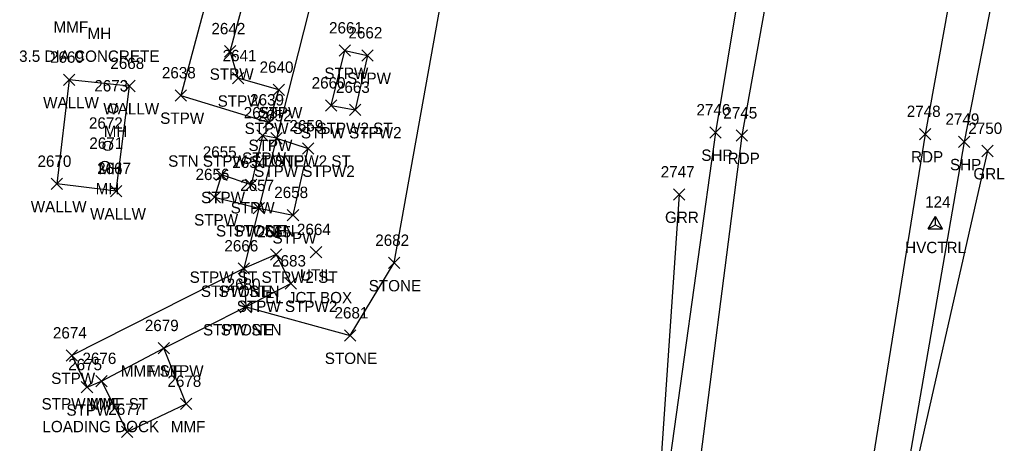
# Model space of a CAD drawing. Extents: x 1443071 to 1445292, y 614024 to 622563.
# Drawn here: x 1443946.8 to 1444119.8, y 620105.8 to 620180.3 of the extents above; entities that cross this region are included whole.
import ezdxf

# ---------------------------------------------------------------- set-up
doc = ezdxf.new("R2010")
doc.units = 0
for name, color, linetype in [('C_A', 7, 'Continuous'), ('C_I', 7, 'Continuous'), ('CPSM', 7, 'Continuous'), ('L_A', 7, 'Continuous'), ('L_C', 7, 'Continuous'), ('L_I', 7, 'Continuous'), ('L_TIC', 7, 'Continuous'), ('LASF', 7, 'Continuous'), ('LBF', 7, 'Continuous'), ('LDEFAULT', 7, 'Continuous'), ('LW', 7, 'Continuous'), ('P_A', 7, 'Continuous'), ('P_I', 7, 'Continuous'), ('P_TIC', 7, 'Continuous'), ('PET', 7, 'Continuous'), ('PSP', 7, 'Continuous'), ('R_A', 7, 'Continuous'), ('R_I', 7, 'Continuous'), ('R_TIC', 7, 'Continuous'), ('RGR', 7, 'Continuous'), ('U_A', 7, 'Continuous'), ('U_C', 7, 'Continuous'), ('U_I', 7, 'Continuous'), ('UDEFAULT', 7, 'Continuous'), ('UUMH', 7, 'Continuous')]:
    doc.layers.add(name, color=color, linetype=linetype)

msp = doc.modelspace()

# ---------------------------------------------------------------- linework, layer by layer
at = {"layer": 'CPSM'}
for p, q in [((1444106.46, 620143.5), (1444107.71, 620145.66)), ((1444106.46, 620143.5), (1444107.71, 620144.22)), ((1444108.96, 620143.5), (1444107.71, 620145.66)), ((1444107.71, 620144.22), (1444107.71, 620145.66)), ((1444107.71, 620144.22), (1444107.71, 620144.22)), ((1444107.71, 620144.22), (1444108.96, 620143.5)), ((1444106.46, 620143.5), (1444108.96, 620143.5))]:
    msp.add_line(p, q, dxfattribs=at)
at = {"layer": 'L_TIC'}
for points in [[(1443982.8, 620173.72), (1443984.8, 620175.72)], [(1443984.8, 620173.72), (1443982.8, 620175.72)], [(1444002.96, 620173.86), (1444004.96, 620175.86)], [(1444004.96, 620173.86), (1444002.96, 620175.86)], [(1444006.94, 620172.99), (1444008.94, 620174.99)], [(1444008.94, 620172.99), (1444006.94, 620174.99)], [(1443954.51, 620168.71), (1443956.51, 620170.71)], [(1443956.51, 620168.71), (1443954.51, 620170.71)], [(1443984.21, 620168.98), (1443986.21, 620170.98)], [(1443986.21, 620168.98), (1443984.21, 620170.98)], [(1443965.09, 620167.62), (1443967.09, 620169.62)], [(1443967.09, 620167.62), (1443965.09, 620169.62)], [(1443991.36, 620166.94), (1443993.36, 620168.94)], [(1443993.36, 620166.94), (1443991.36, 620168.94)], [(1443974.11, 620165.96), (1443976.11, 620167.96)], [(1443976.11, 620165.96), (1443974.11, 620167.96)], [(1444000.56, 620164.18), (1444002.56, 620166.18)], [(1444002.56, 620164.18), (1444000.56, 620166.18)], [(1444000.56, 620164.18), (1444002.56, 620166.18)], [(1444002.56, 620164.18), (1444000.56, 620166.18)], [(1444004.74, 620163.41), (1444006.74, 620165.41)], [(1444006.74, 620163.41), (1444004.74, 620165.41)], [(1444004.74, 620163.41), (1444006.74, 620165.41)], [(1444006.74, 620163.41), (1444004.74, 620165.41)], [(1443989.62, 620161.19), (1443991.62, 620163.19)], [(1443991.62, 620161.19), (1443989.62, 620163.19)], [(1443988.49, 620158.93), (1443990.49, 620160.93)], [(1443990.49, 620158.93), (1443988.49, 620160.93)], [(1443990.95, 620158.42), (1443992.95, 620160.42)], [(1443992.95, 620158.42), (1443990.95, 620160.42)], [(1443990.95, 620158.42), (1443992.95, 620160.42)], [(1443992.95, 620158.42), (1443990.95, 620160.42)], [(1443990.95, 620158.42), (1443992.95, 620160.42)], [(1443992.95, 620158.42), (1443990.95, 620160.42)], [(1443996.52, 620156.64), (1443998.52, 620158.64)], [(1443998.52, 620156.64), (1443996.52, 620158.64)], [(1443996.52, 620156.64), (1443998.52, 620158.64)], [(1443998.52, 620156.64), (1443996.52, 620158.64)], [(1443981.29, 620152.01), (1443983.29, 620154.01)], [(1443983.29, 620152.01), (1443981.29, 620154.01)], [(1443952.34, 620150.4), (1443954.34, 620152.4)], [(1443954.34, 620150.4), (1443952.34, 620152.4)], [(1443952.34, 620150.4), (1443954.34, 620152.4)], [(1443954.34, 620150.4), (1443952.34, 620152.4)], [(1443962.77, 620149.14), (1443964.77, 620151.14)], [(1443964.77, 620149.14), (1443962.77, 620151.14)], [(1443962.77, 620149.14), (1443964.77, 620151.14)], [(1443964.77, 620149.14), (1443962.77, 620151.14)], [(1443986.49, 620150.21), (1443988.49, 620152.21)], [(1443988.49, 620150.21), (1443986.49, 620152.21)], [(1443980.07, 620148.08), (1443982.07, 620150.08)], [(1443982.07, 620148.08), (1443980.07, 620150.08)], [(1443987.85, 620146.15), (1443989.85, 620148.15)], [(1443989.85, 620146.15), (1443987.85, 620148.15)], [(1443987.85, 620146.15), (1443989.85, 620148.15)], [(1443989.85, 620146.15), (1443987.85, 620148.15)], [(1443993.84, 620144.91), (1443995.84, 620146.91)], [(1443995.84, 620144.91), (1443993.84, 620146.91)], [(1443990.9, 620138), (1443992.9, 620140)], [(1443992.9, 620138), (1443990.9, 620140)], [(1443990.9, 620138), (1443992.9, 620140)], [(1443992.9, 620138), (1443990.9, 620140)], [(1443985.19, 620135.52), (1443987.19, 620137.52)], [(1443987.19, 620135.52), (1443985.19, 620137.52)], [(1443985.19, 620135.52), (1443987.19, 620137.52)], [(1443987.19, 620135.52), (1443985.19, 620137.52)], [(1444011.6, 620136.5), (1444013.6, 620138.5)], [(1444013.6, 620136.5), (1444011.6, 620138.5)], [(1443993.47, 620132.87), (1443995.47, 620134.87)], [(1443995.47, 620132.87), (1443993.47, 620134.87)], [(1443993.47, 620132.87), (1443995.47, 620134.87)], [(1443995.47, 620132.87), (1443993.47, 620134.87)], [(1443985.57, 620128.75), (1443987.57, 620130.75)], [(1443987.57, 620128.75), (1443985.57, 620130.75)], [(1443985.57, 620128.75), (1443987.57, 620130.75)], [(1443987.57, 620128.75), (1443985.57, 620130.75)], [(1444003.87, 620123.73), (1444005.87, 620125.73)], [(1444005.87, 620123.73), (1444003.87, 620125.73)], [(1443971.12, 620121.51), (1443973.12, 620123.51)], [(1443973.12, 620121.51), (1443971.12, 620123.51)], [(1443971.12, 620121.51), (1443973.12, 620123.51)], [(1443973.12, 620121.51), (1443971.12, 620123.51)], [(1443954.95, 620120.21), (1443956.95, 620122.21)], [(1443956.95, 620120.21), (1443954.95, 620122.21)], [(1443957.64, 620114.63), (1443959.64, 620116.63)], [(1443959.64, 620114.63), (1443957.64, 620116.63)], [(1443960.2, 620115.72), (1443962.2, 620117.72)], [(1443962.2, 620115.72), (1443960.2, 620117.72)], [(1443960.2, 620115.72), (1443962.2, 620117.72)], [(1443962.2, 620115.72), (1443960.2, 620117.72)], [(1443975.08, 620111.7), (1443977.08, 620113.7)], [(1443977.08, 620111.7), (1443975.08, 620113.7)], [(1443964.69, 620106.77), (1443966.69, 620108.77)], [(1443966.69, 620106.77), (1443964.69, 620108.77)]]:
    msp.add_lwpolyline(points, dxfattribs=at)
at = {"layer": 'LASF'}
msp.add_lwpolyline([(1443976.5, 620204.31), (1443981.5, 620202.34), (1443985.13, 620204.36), (1443990.03, 620197.9), (1443997.43, 620196.31), (1443999.37, 620195.62), (1444001.92, 620195.04), (1443998.63, 620185.84), (1443991.95, 620159.42), (1443988.85, 620147.15), (1443986.19, 620136.52), (1443986.57, 620129.75), (1444004.87, 620124.73), (1444012.6, 620137.5), (1444022.51, 620192.75), (1444029.87, 620218.3), (1444026.72, 620219.74), (1444027.45, 620223.51), (1444031.72, 620223.15), (1444037.34, 620241.52)], dxfattribs=at)
at = {"layer": 'LBF'}
for points in [[(1443985.13, 620204.36), (1443975.11, 620166.96), (1443990.62, 620162.19), (1443992.36, 620167.94), (1443985.21, 620169.98), (1443983.8, 620174.72), (1443990.03, 620197.9)], [(1444001.56, 620165.18), (1444003.96, 620174.86), (1444007.94, 620173.99), (1444005.74, 620164.41)], [(1444001.56, 620165.18), (1444005.74, 620164.41)], [(1443991.95, 620159.42), (1443989.49, 620159.93), (1443987.49, 620151.21), (1443982.29, 620153.01), (1443981.07, 620149.08), (1443988.85, 620147.15), (1443994.84, 620145.91), (1443997.52, 620157.64)], [(1443991.95, 620159.42), (1443997.52, 620157.64)], [(1443991.9, 620139), (1443986.19, 620136.52), (1443955.95, 620121.21), (1443958.64, 620115.63), (1443961.2, 620116.72), (1443972.12, 620122.51), (1443986.57, 620129.75), (1443994.47, 620133.87)], [(1443991.9, 620139), (1443994.47, 620133.87)]]:
    msp.add_lwpolyline(points, dxfattribs=at)
at = {"layer": 'LDEFAULT'}
msp.add_lwpolyline([(1443961.2, 620116.72), (1443965.69, 620107.77), (1443976.08, 620112.7), (1443972.12, 620122.51)], dxfattribs=at)
at = {"layer": 'LW'}
for points in [[(1443963.77, 620150.14), (1443966.09, 620168.62), (1443955.51, 620169.71), (1443953.34, 620151.4)], [(1443963.77, 620150.14), (1443953.34, 620151.4)]]:
    msp.add_lwpolyline(points, dxfattribs=at)
at = {"layer": 'P_TIC'}
for points in [[(1444068.05, 620159.45), (1444070.05, 620161.45)], [(1444070.05, 620159.45), (1444068.05, 620161.45)], [(1444072.72, 620158.9), (1444074.72, 620160.9)], [(1444074.72, 620158.9), (1444072.72, 620160.9)], [(1444104.94, 620159.17), (1444106.94, 620161.17)], [(1444106.94, 620159.17), (1444104.94, 620161.17)], [(1444111.75, 620157.8), (1444113.75, 620159.8)], [(1444113.75, 620157.8), (1444111.75, 620159.8)]]:
    msp.add_lwpolyline(points, dxfattribs=at)
at = {"layer": 'PET'}
for points in [[(1444393.99, 621275.61), (1444360.23, 621155.32), (1444345.74, 621103.98), (1444299.41, 620941.8), (1444273.27, 620844.52), (1444244.09, 620730.97), (1444221.37, 620651.37), (1444196.75, 620548.06), (1444177.44, 620486.23), (1444161.6, 620423.84), (1444143.45, 620356.38), (1444122.97, 620254.68), (1444105.94, 620160.17), (1444094.56, 620089.52), (1444083.91, 620011.71), (1444077.6, 619958.52), (1444073.05, 619913.75)], [(1444350.41, 621238.76), (1444319.14, 621126.97), (1444291.55, 621028.33), (1444258.02, 620908.98), (1444225.45, 620794.19), (1444210.22, 620737.59), (1444176.75, 620619.09), (1444153.1, 620523.45), (1444139.28, 620467.17), (1444131.97, 620435.45), (1444113.12, 620363.38), (1444103.37, 620315.76), (1444093.47, 620268.1), (1444084.86, 620222.29), (1444073.72, 620159.9), (1444065.08, 620092.83), (1444054.27, 620016.44), (1444048.57, 619960.86), (1444043.42, 619916.17), (1444073.05, 619913.75)]]:
    msp.add_lwpolyline(points, dxfattribs=at)
at = {"layer": 'PSP'}
for points in [[(1444228.91, 620648.98), (1444202.76, 620547.52), (1444186.16, 620483.96), (1444170.45, 620422.38), (1444153.07, 620354.47), (1444132.16, 620257.26), (1444128.32, 620238.3), (1444112.75, 620158.8), (1444100.76, 620089.32), (1444087.94, 620010.71), (1444079.9, 619958.71), (1444074.06, 619920.41), (1444074.5, 619920), (1444074.51, 619919.99), (1444073.05, 619913.75)], [(1444173.15, 620620.17), (1444162.97, 620582.35), (1444145.76, 620516.18), (1444133.67, 620469.15), (1444125.56, 620436.17), (1444114.52, 620389.82), (1444108.73, 620364.47), (1444098.18, 620317.14), (1444089.01, 620271.12), (1444079.56, 620223.77), (1444069.05, 620160.45), (1444059.79, 620093.6), (1444051.39, 620014.62), (1444046.92, 619961.11), (1444044.18, 619924.22), (1444043.48, 619922.84), (1444043.42, 619916.17)]]:
    msp.add_lwpolyline(points, dxfattribs=at)
at = {"layer": 'R_TIC'}
for points in [[(1444115.85, 620156.19), (1444117.85, 620158.19)], [(1444117.85, 620156.19), (1444115.85, 620158.19)], [(1444061.71, 620148.53), (1444063.71, 620150.53)], [(1444063.71, 620148.53), (1444061.71, 620150.53)]]:
    msp.add_lwpolyline(points, dxfattribs=at)
at = {"layer": 'RGR'}
for points in [[(1444116.85, 620157.19), (1444101.49, 620089.2), (1444088.76, 620010.5), (1444080.64, 619958.46), (1444074.63, 619920.83)], [(1444062.71, 620149.53), (1444058.87, 620093.77), (1444050.68, 620014.64), (1444046.19, 619961.04), (1444043.36, 619924.56)]]:
    msp.add_lwpolyline(points, dxfattribs=at)
at = {"layer": 'UDEFAULT'}
for points in [[(1443997.88, 620138.4), (1443999.88, 620140.4)], [(1443999.88, 620138.4), (1443997.88, 620140.4)]]:
    msp.add_lwpolyline(points, dxfattribs=at)
at = {"layer": 'UUMH'}
for p, q in [((1443963.22, 620164.66), (1443963.22, 620164.66)), ((1443964.06, 620164.66), (1443964.06, 620164.66)), ((1443962.29, 620158.11), (1443962.29, 620158.11)), ((1443963.12, 620158.11), (1443963.12, 620158.11)), ((1443961.79, 620154.57), (1443961.79, 620154.57)), ((1443962.62, 620154.57), (1443962.62, 620154.57))]:
    msp.add_line(p, q, dxfattribs=at)
for centre in [(1443963.22, 620164.66), (1443962.29, 620158.11), (1443961.79, 620154.57)]:
    msp.add_circle(centre, 0.833, dxfattribs=at)

# ---------------------------------------------------------------- texts
at = {"layer": 'C_A'}
msp.add_text('HVCTRL', height=2, dxfattribs=at).set_placement((1444102.4, 620139.22))
at = {"layer": 'C_I'}
msp.add_text('124', height=2, dxfattribs=at).set_placement((1444105.91, 620147.22))
at = {"layer": 'L_A'}
for s, p in [('MMF', (1443952.76, 620177.99)), ('STPW', (1443980.2, 620169.72)), ('STPW', (1444000.35, 620169.86)), ('STPW', (1444004.33, 620168.99)), ('WALLW', (1443950.93, 620164.71)), ('STPW', (1443981.6, 620164.98)), ('WALLW', (1443961.51, 620163.62)), ('STPW', (1443988.76, 620162.94)), ('STPW', (1443971.5, 620161.96)), ('STPW ST STPW2 ST', (1443986.33, 620160.18)), ('STPW ST STPW2 ST', (1443986.33, 620160.18)), ('STPW STPW2', (1443996.23, 620159.41)), ('STPW STPW2', (1443996.23, 620159.41)), ('STPW', (1443987.01, 620157.19)), ('STN STPW ST STPW2 ST', (1443972.9, 620154.42)), ('STN STPW ST STPW2 ST', (1443972.9, 620154.42)), ('STPW', (1443985.88, 620154.93)), ('STONE', (1443987.49, 620154.42)), ('STPW STPW2', (1443988.01, 620152.64)), ('STPW STPW2', (1443988.01, 620152.64)), ('STPW', (1443978.68, 620148.01)), ('WALLW', (1443948.76, 620146.4)), ('WALLW', (1443948.76, 620146.4)), ('STPW', (1443983.88, 620146.21)), ('WALLW', (1443959.19, 620145.14)), ('WALLW', (1443959.19, 620145.14)), ('STPW', (1443977.46, 620144.08)), ('STPW STN', (1443981.3, 620142.15)), ('STONE', (1443984.4, 620142.15)), ('STPW', (1443991.24, 620140.91)), ('STPW ST STPW2 ST', (1443976.67, 620134)), ('STPW ST STPW2 ST', (1443976.67, 620134)), ('STONE', (1444008.14, 620132.5)), ('STPW STN', (1443978.64, 620131.52)), ('STONE', (1443981.74, 620131.52)), ('STPW STPW2', (1443984.95, 620128.87)), ('STPW STPW2', (1443984.95, 620128.87)), ('STPW STN', (1443979.02, 620124.75)), ('STONE', (1443982.12, 620124.75)), ('STONE', (1444000.42, 620119.73)), ('STPW', (1443952.35, 620116.21)), ('MMF STPW', (1443964.57, 620117.51)), ('MMF', (1443969.4, 620117.51)), ('STPW MMF ST', (1443950.66, 620111.72)), ('MMF', (1443958.49, 620111.72)), ('STPW', (1443955.03, 620110.63)), ('MMF', (1443973.36, 620107.7))]:
    msp.add_text(s, height=2, dxfattribs=at).set_placement(p)
at = {"layer": 'L_C'}
msp.add_text('LOADING DOCK', height=2, dxfattribs=at).set_placement((1443950.81, 620107.72))
at = {"layer": 'L_I'}
for s, p in [('2642', (1443980.5, 620177.72)), ('2661', (1444001.17, 620177.86)), ('2662', (1444004.58, 620176.99)), ('2669', (1443952.15, 620172.71)), ('2668', (1443962.74, 620171.62)), ('2641', (1443982.47, 620172.98)), ('2638', (1443971.8, 620169.96)), ('2640', (1443988.97, 620170.94)), ('2660', (1443998.12, 620168.18)), ('2660', (1443998.12, 620168.18)), ('2663', (1444002.38, 620167.41)), ('2663', (1444002.38, 620167.41)), ('2639', (1443987.3, 620165.19)), ('2653', (1443986.18, 620162.93)), ('2652', (1443988.64, 620162.42)), ('2652', (1443988.64, 620162.42)), ('2652', (1443988.64, 620162.42)), ('2659', (1443994.21, 620160.64)), ('2659', (1443994.21, 620160.64)), ('2655', (1443978.98, 620156.01)), ('2670', (1443949.94, 620154.4)), ('2670', (1443949.94, 620154.4)), ('2654', (1443984.18, 620154.21)), ('2667', (1443960.42, 620153.14)), ('2667', (1443960.42, 620153.14)), ('2656', (1443977.71, 620152.08)), ('2657', (1443985.55, 620150.15)), ('2657', (1443985.55, 620150.15)), ('2658', (1443991.54, 620148.91)), ('2665', (1443988.55, 620142)), ('2665', (1443988.55, 620142)), ('2682', (1444009.29, 620140.5)), ('2666', (1443982.78, 620139.52)), ('2666', (1443982.78, 620139.52)), ('2683', (1443991.16, 620136.87)), ('2683', (1443991.16, 620136.87)), ('2680', (1443983.18, 620132.75)), ('2680', (1443983.18, 620132.75)), ('2681', (1444002.13, 620127.73)), ('2679', (1443968.8, 620125.51)), ('2679', (1443968.8, 620125.51)), ('2674', (1443952.65, 620124.21)), ('2676', (1443957.84, 620119.72)), ('2676', (1443957.84, 620119.72)), ('2675', (1443955.33, 620118.63)), ('2678', (1443972.77, 620115.7)), ('2677', (1443962.39, 620110.77))]:
    msp.add_text(s, height=2, dxfattribs=at).set_placement(p)
at = {"layer": 'P_A'}
for s, p in [('SHP', (1444066.58, 620155.45)), ('RDP', (1444071.21, 620154.9)), ('RDP', (1444103.43, 620155.17)), ('SHP', (1444110.28, 620153.8))]:
    msp.add_text(s, height=2, dxfattribs=at).set_placement(p)
at = {"layer": 'P_I'}
for s, p in [('2746', (1444065.73, 620163.45)), ('2745', (1444070.46, 620162.9)), ('2748', (1444102.68, 620163.17)), ('2749', (1444109.48, 620161.8))]:
    msp.add_text(s, height=2, dxfattribs=at).set_placement(p)
at = {"layer": 'R_A'}
for s, p in [('GRL', (1444114.39, 620152.19)), ('GRR', (1444060.2, 620144.53))]:
    msp.add_text(s, height=2, dxfattribs=at).set_placement(p)
at = {"layer": 'R_I'}
for s, p in [('2750', (1444113.5, 620160.19)), ('2747', (1444059.45, 620152.53))]:
    msp.add_text(s, height=2, dxfattribs=at).set_placement(p)
at = {"layer": 'U_A'}
for s, p in [('MH', (1443958.73, 620176.87)), ('MH', (1443961.58, 620159.66)), ('MH', (1443960.65, 620153.11)), ('MH', (1443960.15, 620149.57)), ('UTIL', (1443996.05, 620134.4))]:
    msp.add_text(s, height=2, dxfattribs=at).set_placement(p)
at = {"layer": 'U_C'}
for s, p in [('3.5 DIA CONCRETE', (1443946.71, 620172.87)), ('EL JCT BOX', (1443989.92, 620130.4))]:
    msp.add_text(s, height=2, dxfattribs=at).set_placement(p)
at = {"layer": 'U_I'}
for s, p in [('2673', (1443959.92, 620167.66)), ('2672', (1443958.98, 620161.11)), ('2671', (1443959.05, 620157.57)), ('2664', (1443995.53, 620142.4))]:
    msp.add_text(s, height=2, dxfattribs=at).set_placement(p)

doc.saveas('drawing.dxf')
